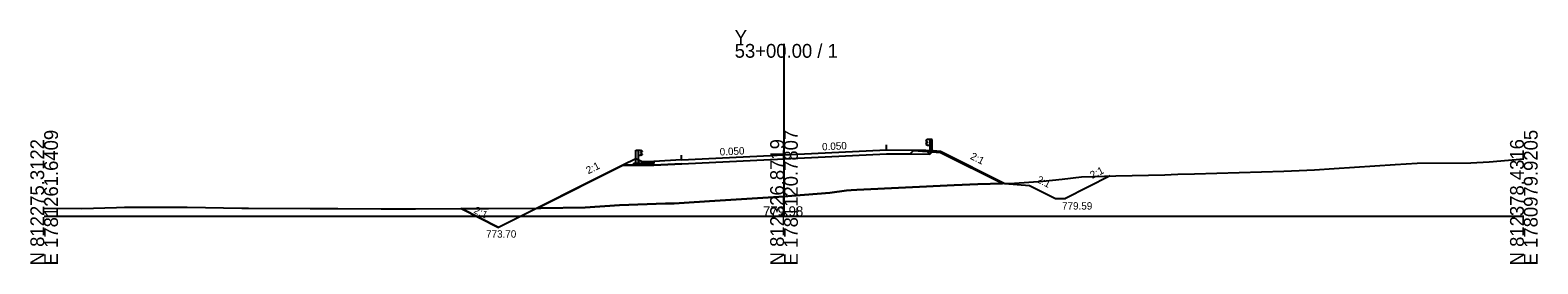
# Model space of a CAD drawing. Extents: x -12583 to 5303, y -44 to 25667.
# Drawn here: x 3997.2 to 4302.8, y 3490.3 to 3537.7 of the extents above; entities that cross this region are included whole.
import ezdxf

# ---------------------------------------------------------------- set-up
doc = ezdxf.new("R2010")
doc.units = 0
for name, color, linetype in [('Exist Cross Section Cell', 7, 'Continuous'), ('Exist XS Center Line Elevation Label', 7, 'Continuous'), ('Exist XS Ground Line', 7, 'Continuous'), ('Prop XS DDE', 7, 'Continuous'), ('Prop XS Ditch Standard Text', 7, 'Continuous'), ('Prop XS Dump Level', 7, 'Continuous'), ('Prop XS Earthwork Shape', 7, 'Continuous'), ('Prop XS EOT Tick Mark', 7, 'Continuous'), ('Prop XS Finish Grade', 7, 'Continuous'), ('Prop XS Finish Grade CurbGutter', 7, 'Continuous'), ('Prop XS Finish Grade Earthwork', 7, 'Continuous'), ('Prop XS Finish Grade Paved Shoulder', 7, 'Continuous'), ('Prop XS Finish Grade Pavement', 7, 'Continuous'), ('Prop XS Guardrail', 7, 'Continuous'), ('Prop XS Pvmt Edge Slope', 7, 'Continuous'), ('Prop XS SE Text', 7, 'Continuous'), ('Prop XS Side Slope Text', 7, 'Continuous'), ('Prop XS Subgrade CurbGutter', 7, 'Continuous'), ('Prop XS Subgrade Earthwork', 7, 'Continuous')]:
    doc.layers.add(name, color=color, linetype=linetype)

msp = doc.modelspace()

# ---------------------------------------------------------------- linework, layer by layer
at = {"layer": 'Exist Cross Section Cell'}
for p, q in [((4150, 3500), (4150, 3534.9)), ((4000, 3500), (4150, 3500)), ((4150, 3500), (4300, 3500))]:
    msp.add_line(p, q, dxfattribs=at)
at = {"layer": 'Exist XS Ground Line'}
for p, q in [((4251.35, 3509.07), (4257.53, 3509.35)), ((4257.53, 3509.35), (4261.52, 3509.66)), ((4261.52, 3509.66), (4273.91, 3510.45)), ((4273.91, 3510.45), (4278.38, 3510.72)), ((4278.38, 3510.72), (4289.25, 3510.8)), ((4289.25, 3510.8), (4292.99, 3511.02)), ((4292.99, 3511.02), (4300, 3511.63)), ((4164.76, 3505.33), (4184.52, 3506.29)), ((4184.52, 3506.29), (4189.32, 3506.44)), ((4189.32, 3506.44), (4196.74, 3506.7)), ((4196.74, 3506.7), (4199.62, 3506.89)), ((4199.62, 3506.89), (4202.51, 3507.05)), ((4202.51, 3507.05), (4206.38, 3507.5)), ((4206.38, 3507.5), (4210.34, 3507.95)), ((4210.34, 3507.95), (4217.26, 3508.16)), ((4217.26, 3508.16), (4227.24, 3508.39)), ((4227.24, 3508.39), (4228.52, 3508.41)), ((4228.52, 3508.41), (4229.85, 3508.47)), ((4229.85, 3508.47), (4233.21, 3508.57)), ((4233.21, 3508.57), (4251.35, 3509.07)), ((4134.91, 3503.02), (4150, 3503.98)), ((4150, 3503.98), (4151.58, 3504.08)), ((4151.58, 3504.08), (4159.27, 3504.69)), ((4159.27, 3504.69), (4162.69, 3505.16)), ((4162.69, 3505.16), (4163.61, 3505.25)), ((4163.61, 3505.25), (4164.76, 3505.33)), ((4000, 3501.59), (4007.62, 3501.56)), ((4007.62, 3501.56), (4014.68, 3501.76)), ((4014.68, 3501.76), (4016.29, 3501.77)), ((4016.29, 3501.77), (4029, 3501.8)), ((4029, 3501.8), (4040.09, 3501.63)), ((4040.09, 3501.63), (4041.45, 3501.61)), ((4041.45, 3501.61), (4053.92, 3501.53)), ((4053.92, 3501.53), (4057.99, 3501.51)), ((4057.99, 3501.51), (4058.34, 3501.51)), ((4058.34, 3501.51), (4058.77, 3501.51)), ((4058.77, 3501.51), (4059.54, 3501.5)), ((4059.54, 3501.5), (4068.35, 3501.49)), ((4068.35, 3501.49), (4075.32, 3501.46)), ((4075.32, 3501.46), (4086.61, 3501.51)), ((4086.61, 3501.51), (4090.12, 3501.56)), ((4090.12, 3501.56), (4100.72, 3501.63)), ((4100.72, 3501.63), (4109.69, 3501.71)), ((4109.69, 3501.71), (4116.62, 3502.18)), ((4116.62, 3502.18), (4125.97, 3502.52)), ((4125.97, 3502.52), (4127.72, 3502.56)), ((4127.72, 3502.56), (4129.73, 3502.66)), ((4129.73, 3502.66), (4134.91, 3503.02))]:
    msp.add_line(p, q, dxfattribs=at)
at = {"layer": 'Prop XS DDE'}
for p, q in [((4194.8, 3506.63), (4199.8, 3506.21)), ((4199.8, 3506.21), (4205.04, 3503.59)), ((4216.12, 3508.13), (4207.04, 3503.59)), ((4205.04, 3503.59), (4207.04, 3503.59))]:
    msp.add_line(p, q, dxfattribs=at)
at = {"layer": 'Prop XS Dump Level'}
for p, q in [((4129.25, 3511.37), (4150, 3512.41)), ((4150, 3512.41), (4170.75, 3513.45))]:
    msp.add_line(p, q, dxfattribs=at)
at = {"layer": 'Prop XS Earthwork Shape'}
for points in [[(4129.29, 3510.58), (4150.04, 3511.62), (4170.77, 3512.65), (4175.55, 3512.61), (4176.24, 3513.3), (4181.75, 3512.92), (4194.35, 3506.61), (4189.32, 3506.44), (4184.52, 3506.29), (4164.76, 3505.33), (4163.61, 3505.25), (4162.69, 3505.16), (4159.27, 3504.69), (4151.58, 3504.08), (4150, 3503.98), (4134.91, 3503.02), (4129.73, 3502.66), (4127.72, 3502.56), (4125.97, 3502.52), (4116.62, 3502.18), (4109.69, 3501.71), (4100.72, 3501.63), (4099.98, 3501.62), (4117.32, 3510.29), (4119.19, 3510.29), (4123.58, 3510.29)], [(4086.61, 3501.51), (4090.12, 3501.56), (4099.98, 3501.62), (4092.13, 3497.7), (4084.54, 3501.5)]]:
    msp.add_lwpolyline(points, close=True, dxfattribs=at)
at = {"layer": 'Prop XS EOT Tick Mark'}
for p, q in [((4129.25, 3511.37), (4129.25, 3512.37)), ((4170.75, 3513.45), (4170.75, 3514.45))]:
    msp.add_line(p, q, dxfattribs=at)
at = {"layer": 'Prop XS Finish Grade'}
for p, q in [((4178.75, 3513.37), (4180.24, 3513.26)), ((4119.98, 3511.62), (4117.32, 3510.29)), ((4120.56, 3511.33), (4119.98, 3511.62))]:
    msp.add_line(p, q, dxfattribs=at)
at = {"layer": 'Prop XS Finish Grade CurbGutter'}
for p, q in [((4121.25, 3510.99), (4120.56, 3511.33)), ((4123.58, 3511.09), (4121.25, 3510.99))]:
    msp.add_line(p, q, dxfattribs=at)
at = {"layer": 'Prop XS Finish Grade Earthwork'}
for p, q in [((4180.24, 3513.26), (4181.75, 3513.16)), ((4181.75, 3513.16), (4194.8, 3506.63)), ((4117.32, 3510.29), (4092.13, 3497.7)), ((4084.54, 3501.5), (4092.13, 3497.7))]:
    msp.add_line(p, q, dxfattribs=at)
at = {"layer": 'Prop XS Finish Grade Paved Shoulder'}
for p, q in [((4170.75, 3513.45), (4178.75, 3513.37)), ((4129.25, 3511.37), (4123.58, 3511.09))]:
    msp.add_line(p, q, dxfattribs=at)
at = {"layer": 'Prop XS Finish Grade Pavement'}
for p, q in [((4129.25, 3511.37), (4150, 3512.41)), ((4150, 3512.41), (4170.75, 3513.45))]:
    msp.add_line(p, q, dxfattribs=at)
at = {"layer": 'Prop XS Guardrail'}
for p, q in [((4179.07, 3515.53), (4178.78, 3515.33)), ((4179.57, 3515.53), (4179.07, 3515.53)), ((4180.07, 3515.53), (4179.57, 3515.53)), ((4179.57, 3515.53), (4179.57, 3513.03)), ((4180.07, 3513.03), (4180.07, 3515.53)), ((4119.93, 3513.39), (4120.43, 3513.39)), ((4119.93, 3510.89), (4119.93, 3513.39)), ((4120.43, 3513.39), (4120.93, 3513.39)), ((4120.43, 3513.39), (4120.43, 3510.89)), ((4120.93, 3513.39), (4121.22, 3513.19)), ((4121.22, 3513.07), (4120.93, 3512.87)), ((4120.93, 3512.87), (4120.93, 3512.77)), ((4120.93, 3512.77), (4121.22, 3512.57)), ((4121.22, 3512.45), (4120.93, 3512.25)), ((4121.22, 3513.19), (4121.25, 3513.13)), ((4121.25, 3513.13), (4121.22, 3513.07)), ((4121.22, 3512.57), (4121.25, 3512.51)), ((4121.25, 3512.51), (4121.22, 3512.45)), ((4178.78, 3515.33), (4178.75, 3515.27)), ((4178.75, 3515.27), (4178.78, 3515.21)), ((4178.78, 3514.72), (4178.75, 3514.66)), ((4178.75, 3514.66), (4178.78, 3514.6)), ((4178.78, 3515.21), (4179.07, 3515.01)), ((4179.07, 3514.92), (4178.78, 3514.72)), ((4178.78, 3514.6), (4179.07, 3514.4)), ((4179.07, 3515.01), (4179.07, 3514.92)), ((4179.07, 3514.4), (4179.57, 3514.4)), ((4120.93, 3512.25), (4120.43, 3512.25))]:
    msp.add_line(p, q, dxfattribs=at)
at = {"layer": 'Prop XS Pvmt Edge Slope'}
for p, q in [((4178.75, 3513.37), (4179.55, 3512.57)), ((4119.56, 3510.67), (4119.19, 3510.29)), ((4120.56, 3510.67), (4119.56, 3510.67))]:
    msp.add_line(p, q, dxfattribs=at)
at = {"layer": 'Prop XS Subgrade CurbGutter'}
for p, q in [((4120.56, 3510.67), (4120.56, 3511.33)), ((4123.58, 3510.67), (4120.56, 3510.67)), ((4123.58, 3511.09), (4123.58, 3510.67))]:
    msp.add_line(p, q, dxfattribs=at)
at = {"layer": 'Prop XS Subgrade Earthwork'}
for p, q in [((4150.04, 3511.62), (4170.77, 3512.65)), ((4170.77, 3512.65), (4179.55, 3512.57)), ((4179.55, 3512.57), (4180.24, 3513.26)), ((4119.19, 3510.29), (4117.32, 3510.29)), ((4123.58, 3510.29), (4119.19, 3510.29)), ((4129.29, 3510.58), (4123.58, 3510.29)), ((4129.29, 3510.58), (4150.04, 3511.62))]:
    msp.add_line(p, q, dxfattribs=at)

# ---------------------------------------------------------------- texts
at = {"layer": 'Exist Cross Section Cell'}
for s, p in [('Y', (4140, 3534.9)), ('53+00.00 / 1', (4140, 3532.1))]:
    msp.add_text(s, height=2.8, dxfattribs=at).set_placement(p)
for s, p in [('N 812275.3122', (4000, 3490)), ('E 1781261.6409', (4002.8, 3490)), ('N 812326.8719', (4150, 3490)), ('E 1781120.7807', (4152.8, 3490)), ('N 812378.4316', (4300, 3490)), ('E 1780979.9205', (4302.8, 3490))]:
    msp.add_text(s, height=2.8, rotation=90, dxfattribs=at).set_placement(p)
at = {"layer": 'Exist XS Center Line Elevation Label'}
msp.add_text('779.98', height=2, dxfattribs=at).set_placement((4145.73, 3499.98))
at = {"layer": 'Prop XS Ditch Standard Text'}
for s, p in [('779.59', (4206.37, 3501.31)), ('773.70', (4089.59, 3495.62))]:
    msp.add_text(s, height=1.5, dxfattribs=at).set_placement(p)
at = {"layer": 'Prop XS Dump Level'}
msp.add_text('Case2', height=0.04, dxfattribs=at).set_placement((4178.75, 3513.09))
at = {"layer": 'Prop XS SE Text'}
for p in [(4137, 3512.26), (4157.75, 3513.3)]:
    msp.add_text('0.050', height=1.5, rotation=2.8624, dxfattribs=at).set_placement(p)
at = {"layer": 'Prop XS Side Slope Text'}
for rotation, p in [(333.4349, (4187.64, 3511.65)), (26.5651, (4110.32, 3508.47)), (26.5651, (4212.5, 3507.52)), (333.4349, (4201.1, 3506.92)), (333.4349, (4086.97, 3500.7))]:
    msp.add_text('2:1', height=1.5, rotation=rotation, dxfattribs=at).set_placement(p)

doc.saveas('drawing.dxf')
